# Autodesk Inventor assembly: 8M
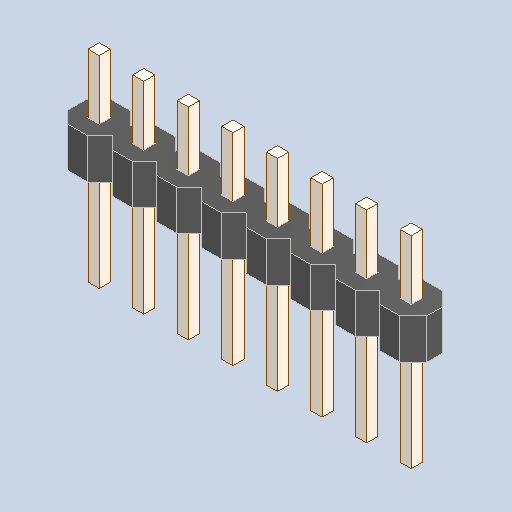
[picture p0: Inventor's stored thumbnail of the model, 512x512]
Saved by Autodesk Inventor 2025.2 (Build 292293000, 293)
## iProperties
Created: 2025-04
Part Number: 8M
Description: PART--DESC
Document SubType Name: Assembly
Designer: BennF
Author: BennF
Revision Number: NONE
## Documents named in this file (3)
- C:\Users\BennF\Nextcloud\Benutzer\CNC JarBeRi\existing parts\Electronics\RepRap A4988 Shied (USE WITHOUT ARDUINO)\reprap-a4988-1.snapshot.1\RepRap\RepRap\8M.iam
- C:\Users\BennF\Nextcloud\Benutzer\CNC JarBeRi\existing parts\Electronics\RepRap A4988 Shied (USE WITHOUT ARDUINO)\reprap-a4988-1.snapshot.1\RepRap\RepRap\8M Geometry.ipt
- C:\Users\BennF\Nextcloud\Benutzer\CNC JarBeRi\existing parts\Electronics\RepRap A4988 Shied (USE WITHOUT ARDUINO)\reprap-a4988-1.snapshot.1\RepRap\RepRap\pin4.ipt
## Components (2 placed, 2 different names)
1. 8M Geometry
2. pin4
